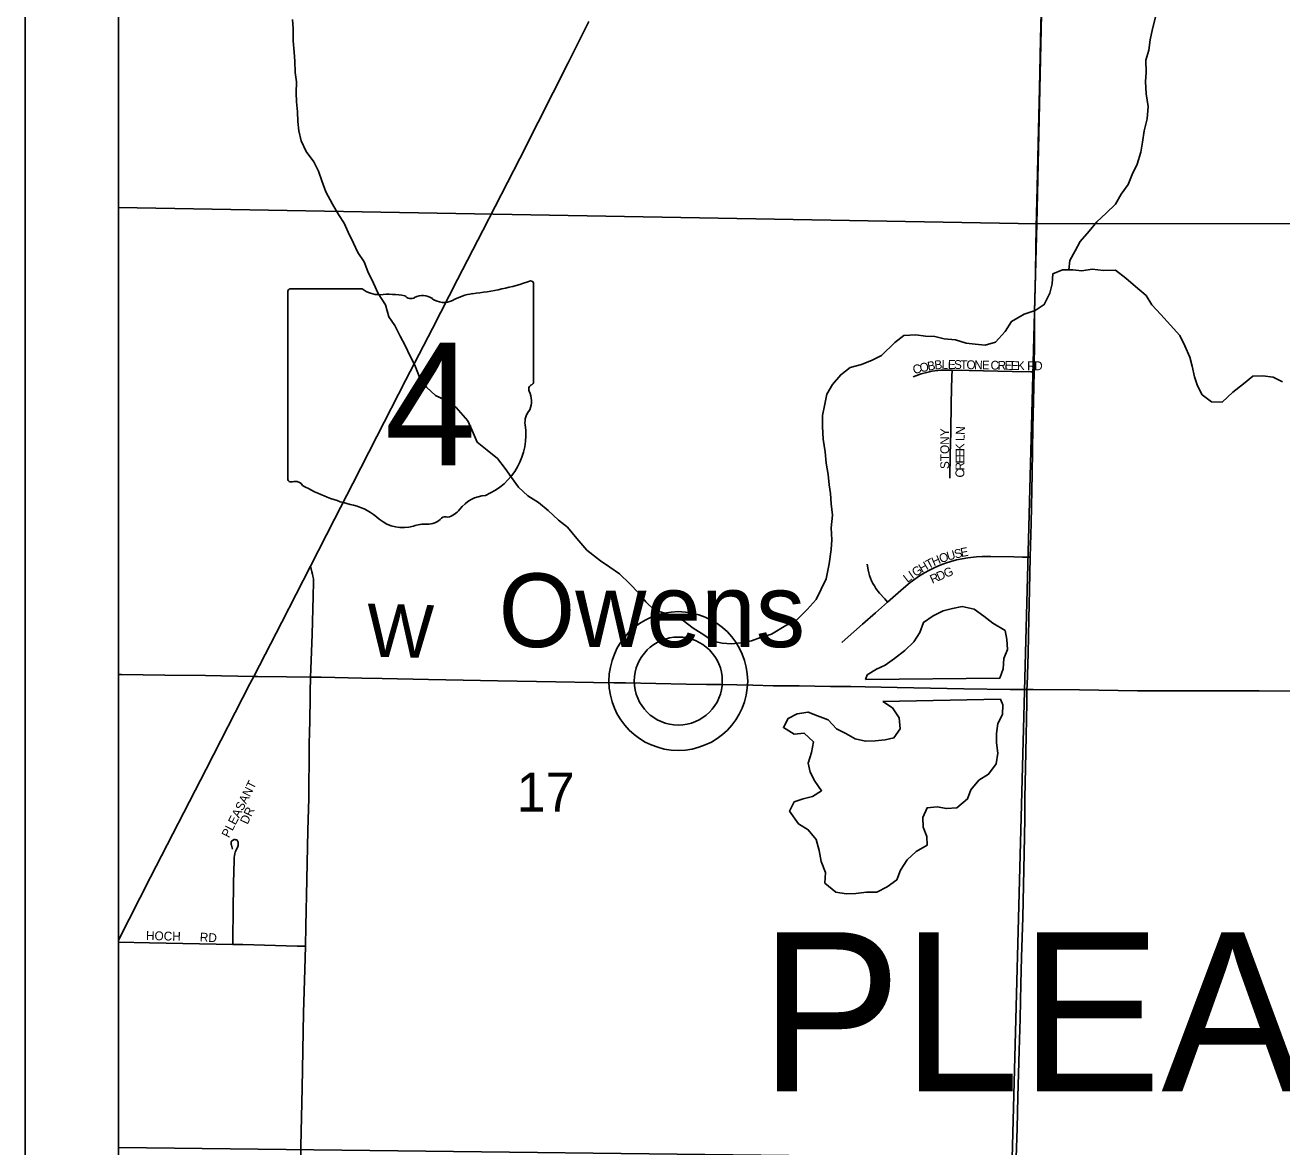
# Model space of a CAD drawing. Extents: x -97 to 34, y -21 to 22.
# Drawn here: x 3.451 to 4.799, y 14.464 to 15.667 of the extents above; entities that cross this region are included whole.
import ezdxf

# ---------------------------------------------------------------- set-up
doc = ezdxf.new("R2010")
doc.units = 0
for name, color, linetype in [('GM_X_County_Road', 7, 'Continuous'), ('GM_X_County_Road_Text', 7, 'Continuous'), ('GM_X_Minor_Lake', 7, 'Continuous'), ('GM_X_Minor_River', 7, 'Continuous'), ('GM_X_Section', 7, 'Continuous'), ('GM_X_Section_Text', 7, 'Continuous'), ('GM_X_State_Location', 7, 'Continuous'), ('GM_X_State_Route', 7, 'Continuous'), ('GM_X_State_Shield', 7, 'Continuous'), ('GM_X_Township_Subdivision', 7, 'Continuous'), ('GM_X_Township_Subdivision_Text', 7, 'Continuous'), ('GM_X_Township_Text', 7, 'Continuous'), ('GM_X_Unincorporated', 7, 'Continuous'), ('GM_X_Unincorporated_Location', 7, 'Continuous'), ('GM_X_Unincorporated_Text', 7, 'Continuous'), ('SH_Data', 7, 'Continuous')]:
    doc.layers.add(name, color=color, linetype=linetype)

msp = doc.modelspace()

# ---------------------------------------------------------------- linework, layer by layer
at = {"layer": 'GM_X_County_Road'}
for points in [[(4.5335, 15.2947), (4.5335, 15.2973), (4.5339, 15.3284), (4.5342, 15.3594), (4.5352, 15.3998), (4.5356, 15.4278), (4.5359, 15.4495), (4.5369, 15.493), (4.5379, 15.5396), (4.5394, 15.5986), (4.5405, 15.6514), (4.5417, 15.695), (4.5426, 15.7478), (4.5432, 15.7726), (4.5441, 15.8037), (4.5446, 15.8379), (4.5452, 15.8658), (4.546, 15.9124), (4.5468, 15.9435), (4.547, 15.959), (4.547, 15.9605)], [(4.5295, 15.0961), (4.5305, 15.1327), (4.5314, 15.1855), (4.5323, 15.2352), (4.533, 15.2631), (4.5335, 15.2947)], [(3.7576, 14.9675), (3.7578, 14.9762), (3.7593, 15.0135), (3.7603, 15.0538), (3.7607, 15.0698), (3.7606, 15.073), (3.7602, 15.0756), (3.7598, 15.0778), (3.7591, 15.0804), (3.7575, 15.0865)], [(4.5259, 14.9544), (4.526, 14.9587), (4.5272, 14.9929), (4.528, 15.0301), (4.5288, 15.0612), (4.5295, 15.0961)], [(3.5515, 14.9704), (3.5547, 14.9703), (3.6013, 14.9696), (3.6449, 14.9692), (3.6968, 14.9683)], [(3.6968, 14.9683), (3.7008, 14.9683), (3.7319, 14.9679), (3.7576, 14.9675)], [(3.752, 14.6791), (3.7526, 14.7006), (3.7537, 14.7506), (3.7548, 14.8031), (3.7557, 14.8376), (3.7559, 14.8557), (3.756, 14.8742), (3.7562, 14.899), (3.7564, 14.9051), (3.7571, 14.9422), (3.7573, 14.9514), (3.7576, 14.9675)], [(3.7576, 14.9675), (3.7691, 14.9673), (3.8126, 14.9665), (3.8344, 14.9661), (3.8841, 14.9651), (3.9586, 14.9637), (4.0208, 14.9623), (4.0611, 14.9617), (4.0829, 14.9615), (4.0953, 14.9613), (4.1605, 14.9599), (4.1822, 14.9596), (4.1977, 14.9595), (4.2319, 14.9588), (4.2536, 14.9582), (4.2815, 14.9581), (4.3153, 14.9576), (4.337, 14.9573), (4.3525, 14.957), (4.3866, 14.9562), (4.4581, 14.9548), (4.5078, 14.9544), (4.5259, 14.9544)], [(4.5028, 14.0177), (4.5034, 14.0361), (4.5047, 14.0827), (4.5064, 14.1573), (4.5074, 14.1977), (4.508, 14.2412), (4.5092, 14.2846), (4.5104, 14.3281), (4.5122, 14.3872), (4.5134, 14.4213), (4.5153, 14.4834), (4.5162, 14.5176), (4.5177, 14.5673), (4.5186, 14.6015), (4.5195, 14.6387), (4.5201, 14.6667), (4.5214, 14.7102), (4.523, 14.7785), (4.5235, 14.8158), (4.5238, 14.8375), (4.5248, 14.8872), (4.5257, 14.9401), (4.5259, 14.9544)], [(4.5259, 14.9544), (4.5326, 14.9543), (4.5823, 14.9538), (4.6444, 14.9529), (4.7034, 14.9529), (4.7314, 14.9528), (4.7749, 14.9529), (4.8339, 14.9526), (4.8773, 14.952), (4.9115, 14.9519), (4.9426, 14.9516), (4.9643, 14.9513), (5.0016, 14.9509), (5.0451, 14.9504), (5.0979, 14.9499), (5.1663, 14.9494), (5.2191, 14.949), (5.2719, 14.9485), (5.31, 14.948)], [(3.737, 14.0177), (3.7376, 14.0393), (3.7389, 14.0827), (3.74, 14.1386), (3.7418, 14.2163), (3.7428, 14.2722), (3.7441, 14.3249), (3.7463, 14.4243), (3.7471, 14.4647), (3.7486, 14.5268), (3.7501, 14.6075), (3.7513, 14.6541), (3.752, 14.6791)]]:
    msp.add_lwpolyline(points, dxfattribs=at)
at = {"layer": 'GM_X_Minor_Lake'}
for points in [[(4.4967, 14.9663), (4.5006, 14.9765), (4.5012, 14.9874), (4.5051, 14.9972), (4.5042, 15.0079), (4.5024, 15.0174), (4.4893, 15.0252), (4.4796, 15.0329), (4.4692, 15.0403), (4.4564, 15.0432), (4.4461, 15.0411), (4.4359, 15.0386), (4.4252, 15.0331), (4.4149, 15.0261), (4.4109, 15.0155), (4.4047, 15.0054), (4.3951, 14.9961), (4.384, 14.9876), (4.374, 14.9802), (4.3645, 14.9762), (4.3546, 14.9699), (4.3526, 14.965)], [(4.3526, 14.965), (4.4967, 14.9663)], [(4.3715, 14.9415), (4.3816, 14.9345), (4.389, 14.9238), (4.3899, 14.912), (4.3833, 14.9023), (4.3738, 14.9002), (4.3632, 14.8992), (4.3526, 14.8987), (4.3417, 14.9015), (4.3316, 14.907), (4.3215, 14.9121), (4.3126, 14.9217), (4.3013, 14.9261), (4.2912, 14.93), (4.2794, 14.928), (4.2699, 14.9232), (4.2648, 14.9134), (4.2764, 14.9064), (4.287, 14.9074), (4.2971, 14.8981), (4.295, 14.8868), (4.2914, 14.8751), (4.2935, 14.8656), (4.2986, 14.856), (4.3056, 14.8456), (4.2961, 14.8394), (4.2858, 14.8369), (4.2763, 14.8336), (4.2713, 14.8239), (4.2809, 14.8101), (4.2913, 14.8038), (4.2999, 14.7934), (4.3031, 14.7816), (4.3051, 14.7698), (4.3099, 14.758), (4.3093, 14.7466), (4.3208, 14.737), (4.3322, 14.7353), (4.3424, 14.7355), (4.3537, 14.7368), (4.3651, 14.737), (4.3761, 14.7428), (4.3865, 14.7502), (4.3904, 14.7604), (4.3974, 14.7717), (4.407, 14.7806), (4.4188, 14.7872), (4.4186, 14.7967), (4.4146, 14.8066), (4.4144, 14.8168), (4.4188, 14.8274), (4.4297, 14.8283), (4.4395, 14.8266), (4.4509, 14.8272), (4.462, 14.8369), (4.4656, 14.8467), (4.4744, 14.8571), (4.4848, 14.8634), (4.4929, 14.8746), (4.4946, 14.886), (4.4932, 14.897), (4.4934, 14.9072), (4.4947, 14.9178), (4.4998, 14.9276), (4.5, 14.9378), (4.4974, 14.9439)], [(4.4974, 14.9439), (4.3715, 14.9415)]]:
    msp.add_lwpolyline(points, dxfattribs=at)
at = {"layer": 'GM_X_Minor_River'}
for points in [[(4.5708, 15.4042), (4.5718, 15.4142), (4.5776, 15.4247), (4.5831, 15.4348), (4.5927, 15.4457), (4.6008, 15.4558), (4.6108, 15.4651), (4.6208, 15.4747), (4.627, 15.4852), (4.6344, 15.4957), (4.6387, 15.5063), (4.6442, 15.5176), (4.6482, 15.5304), (4.6499, 15.5413), (4.6516, 15.5534), (4.6548, 15.5663), (4.6558, 15.5795), (4.6538, 15.5928), (4.6532, 15.6061), (4.6538, 15.6159), (4.6536, 15.6292), (4.6568, 15.6398), (4.6581, 15.6507), (4.6606, 15.6625), (4.665, 15.6794)], [(3.7383, 15.6727), (3.7389, 15.6632), (3.7391, 15.6499), (3.74, 15.6378), (3.7406, 15.6279), (3.7411, 15.6158), (3.7425, 15.6059), (3.7423, 15.5942), (3.7425, 15.5843), (3.7435, 15.5737), (3.744, 15.5634), (3.745, 15.5532), (3.7475, 15.5425), (3.753, 15.5311), (3.7611, 15.5199), (3.7662, 15.51), (3.7698, 15.4997), (3.7738, 15.4879), (3.7811, 15.4748), (3.7874, 15.4637), (3.7937, 15.4542), (3.798, 15.4446), (3.8035, 15.4328)], [(3.8035, 15.4328), (3.8083, 15.4228), (3.8149, 15.4129), (3.8189, 15.4025), (3.8251, 15.3899), (3.8302, 15.3789), (3.8379, 15.3666), (3.8415, 15.354), (3.8478, 15.3444), (3.8536, 15.333), (3.8591, 15.323), (3.8643, 15.3115), (3.8694, 15.302), (3.8745, 15.289), (3.8819, 15.2786), (3.8915, 15.2694), (3.9017, 15.265), (3.9136, 15.2565), (3.9262, 15.2422), (3.931, 15.2319), (3.9364, 15.2193), (3.9469, 15.2108), (3.9581, 15.2019), (3.9662, 15.1911), (3.9732, 15.1815), (3.9806, 15.1712), (3.9907, 15.1619), (4.0019, 15.1549), (4.0123, 15.146), (4.0235, 15.1359), (4.0332, 15.1282), (4.0432, 15.1163), (4.054, 15.1036), (4.0685, 15.0923), (4.0786, 15.0853), (4.0891, 15.0783), (4.0999, 15.0675), (4.1092, 15.0579), (4.117, 15.0483), (4.1266, 15.0394), (4.1364, 15.0366), (4.1462, 15.0326), (4.1571, 15.0283), (4.1679, 15.0201), (4.1795, 15.0127), (4.1892, 15.0061), (4.199, 15.004), (4.2092, 15.0031), (4.2194, 15.0044), (4.2304, 15.0065), (4.2403, 15.0101), (4.2521, 15.0137), (4.2674, 15.0229), (4.2788, 15.0284), (4.2903, 15.04), (4.3, 15.0508), (4.3054, 15.0617), (4.3105, 15.073), (4.3138, 15.0889), (4.316, 15.1044), (4.3165, 15.1146), (4.316, 15.1275), (4.3174, 15.1411), (4.316, 15.1533), (4.3151, 15.1643), (4.3137, 15.1738), (4.3128, 15.1848), (4.3107, 15.1969), (4.3094, 15.2091), (4.3074, 15.2228), (4.3065, 15.2364), (4.3067, 15.2482), (4.3091, 15.2603), (4.3112, 15.2708), (4.3174, 15.2814), (4.3263, 15.2918), (4.3362, 15.2996), (4.3484, 15.3028), (4.3598, 15.3075), (4.3701, 15.3123), (4.3843, 15.3264), (4.3939, 15.3339), (4.4068, 15.3344), (4.4173, 15.3331), (4.4271, 15.3329), (4.4373, 15.3301), (4.4494, 15.3291), (4.4607, 15.3255), (4.4705, 15.3246), (4.481, 15.3233), (4.4921, 15.3265), (4.5025, 15.3381), (4.5094, 15.3489), (4.5228, 15.3567), (4.5346, 15.3606), (4.5445, 15.3669), (4.5504, 15.3793), (4.5528, 15.3891), (4.5538, 15.4001), (4.564, 15.4041), (4.575, 15.4043)], [(4.575, 15.4043), (4.5848, 15.4033), (4.5958, 15.405), (4.6079, 15.4037), (4.6208, 15.4039), (4.632, 15.3953), (4.6424, 15.3864), (4.6539, 15.3767), (4.6598, 15.3668), (4.6695, 15.3564), (4.6799, 15.3448), (4.6899, 15.3337), (4.6954, 15.3226), (4.7005, 15.3107), (4.7033, 15.3008), (4.7058, 15.2894), (4.709, 15.2799), (4.7138, 15.2703), (4.7239, 15.2626), (4.7352, 15.2624), (4.7467, 15.2732), (4.7582, 15.2821), (4.7682, 15.2902), (4.7788, 15.2904), (4.7901, 15.2891), (4.7999, 15.284)]]:
    msp.add_lwpolyline(points, dxfattribs=at)
at = {"layer": 'GM_X_Section'}
for p, q in [((3.5515, 16.4817), (3.5515, 15.4711)), ((3.5515, 15.4711), (3.5515, 14.463))]:
    msp.add_line(p, q, dxfattribs=at)
for points in [[(3.5515, 15.4711), (4.5367, 15.4537), (4.5591, 16.4647), (3.5515, 16.4817)], [(3.5515, 14.463), (4.5101, 14.4515), (4.5367, 15.4537), (3.5515, 15.4711)]]:
    msp.add_lwpolyline(points, dxfattribs=at)
for points in [[(4.5591, 16.4647), (5.5865, 16.4584), (5.5758, 15.4541), (4.5367, 15.4537)], [(4.5367, 15.4537), (5.5758, 15.4541), (5.5564, 14.4458), (4.5101, 14.4515)]]:
    msp.add_lwpolyline(points, close=True, dxfattribs=at)
at = {"layer": 'GM_X_State_Route'}
msp.add_lwpolyline([(3.5515, 14.6855), (3.586, 14.753), (3.6457, 14.8689), (3.6925, 14.9602), (3.6968, 14.9683), (3.7268, 15.0263), (3.7575, 15.0865), (3.7833, 15.137), (3.8028, 15.1751), (3.8286, 15.2254), (3.8599, 15.2862), (3.8883, 15.3415), (3.9153, 15.3939), (3.9422, 15.4464), (3.9821, 15.5238), (4.0017, 15.5625), (4.0339, 15.6263), (4.0561, 15.6707)], dxfattribs=at)
at = {"layer": 'GM_X_State_Shield'}
for p, q in [((3.7332, 15.3805), (3.7332, 15.1804)), ((3.813, 15.384), (3.7358, 15.384)), ((3.9968, 15.2843), (3.9968, 15.389)), ((3.9968, 15.2843), (3.9968, 15.2843))]:
    msp.add_line(p, q, dxfattribs=at)
for centre, radius, start, end in [((3.7362, 15.381), 0.00305, 98.1301, 188.1301), ((3.8314, 15.4072), 0.0296, 231.6195, 271.1119), ((3.9029, 15.6568), 0.2796, 275.8445, 288.9065), ((3.9939, 15.3894), 0.00294, 351.8621, 97.738), ((3.8412, 15.2716), 0.1064, 80.4867, 94.9883), ((3.8653, 15.382), 0.00855, 219.7921, 297.1024), ((3.8779, 15.3589), 0.0178, 54.4667, 119.1411), ((3.9008, 15.3906), 0.0214, 233.8562, 294.8282), ((3.9386, 15.3229), 0.0563, 97.3462, 120.7689), ((3.9961, 15.2766), 0.00454, 107.944, 210.337), ((3.9672, 15.2633), 0.0273, 340.033, 23.6496), ((3.9937, 15.2839), 0.00314, 289.6038, 7.7341), ((4.0073, 15.2405), 0.0198, 136.8065, 186.9296), ((3.9186, 15.2271), 0.0699, 292.3089, 8.9858), ((3.7362, 15.18), 0.00308, 171.9584, 258.3066), ((3.7367, 15.2005), 0.0235, 267.339, 280.6039), ((3.7415, 15.1689), 0.00848, 29.7484, 93.2717), ((3.8485, 15.3487), 0.2019, 240.4129, 257.1985), ((3.7883, 15.0905), 0.0632, 47.1842, 75.836), ((3.9481, 15.1242), 0.0383, 94.4031, 142.5768), ((3.8567, 15.1679), 0.0401, 230.7004, 286.2918), ((3.8828, 15.1529), 0.0214, 268.777, 315.5493), ((3.9021, 15.1335), 0.00601, 65.7517, 132.6484), ((3.8995, 15.161), 0.0226, 282.8732, 323.2771), ((3.8798, 15.0987), 0.0329, 85.6951, 111.2099)]:
    msp.add_arc(centre, radius, start, end, dxfattribs=at)
at = {"layer": 'GM_X_Township_Subdivision'}
for points in [[(4.404, 15.2894), (4.4069, 15.2905), (4.4126, 15.2926), (4.4184, 15.2943), (4.4214, 15.295), (4.4243, 15.2955), (4.4273, 15.296), (4.4334, 15.2965), (4.4425, 15.2967), (4.4456, 15.2967)], [(4.4434, 15.181), (4.4436, 15.2059), (4.4442, 15.2307), (4.4448, 15.2618), (4.4454, 15.2897), (4.4456, 15.2967)], [(4.4456, 15.2967), (4.464, 15.2963), (4.51, 15.2953), (4.53, 15.2948), (4.5335, 15.2947)], [(4.5295, 15.0961), (4.5212, 15.0961), (4.512, 15.0964), (4.4872, 15.0969), (4.4779, 15.0968), (4.4718, 15.0965), (4.4625, 15.0955), (4.4564, 15.0945), (4.4504, 15.0932), (4.4444, 15.0916), (4.4386, 15.0896), (4.4328, 15.0874), (4.4271, 15.0849), (4.4215, 15.0823), (4.4161, 15.0793), (4.4108, 15.0761), (4.4057, 15.0727), (4.4008, 15.0689), (4.3936, 15.063), (4.3765, 15.048)], [(4.3765, 15.048), (4.3734, 15.0514), (4.3677, 15.0576), (4.364, 15.0626), (4.3623, 15.0653), (4.3607, 15.068), (4.3593, 15.0707), (4.3581, 15.0736), (4.357, 15.0765), (4.3562, 15.0795), (4.3555, 15.0826), (4.3545, 15.0887)], [(4.3765, 15.048), (4.3634, 15.0365), (4.3495, 15.0242), (4.331, 15.0078), (4.3273, 15.0046)], [(3.6742, 14.6809), (3.6742, 14.6884), (3.6744, 14.716), (3.6751, 14.7467), (3.6755, 14.7713), (3.6757, 14.7744), (3.6759, 14.7759), (3.6765, 14.7785), (3.6769, 14.7798), (3.6775, 14.7813), (3.6795, 14.786), (3.6799, 14.7869), (3.6801, 14.788), (3.6801, 14.789), (3.68, 14.7898), (3.6799, 14.7906), (3.6797, 14.7912), (3.6793, 14.7919), (3.6787, 14.7925), (3.6781, 14.7929), (3.6773, 14.7931), (3.6765, 14.7933), (3.6757, 14.7933), (3.675, 14.7931), (3.6744, 14.7928), (3.6738, 14.7924), (3.6733, 14.7918), (3.6729, 14.7912), (3.6726, 14.7905), (3.6725, 14.7897), (3.6725, 14.7882), (3.6727, 14.7874), (3.6739, 14.783)], [(3.5515, 14.6833), (3.5849, 14.6825), (3.6742, 14.6809)], [(3.6742, 14.6809), (3.6849, 14.6807), (3.7432, 14.6791), (3.7489, 14.6791), (3.752, 14.6791)]]:
    msp.add_lwpolyline(points, dxfattribs=at)
at = {"layer": 'GM_X_Unincorporated'}
for radius in [0.0744, 0.0472]:
    msp.add_circle((4.152, 14.9633), radius, dxfattribs=at)
at = {"layer": 'GM_X_Unincorporated_Location'}
msp.add_line((4.152, 14.9633), (4.152, 14.9633), dxfattribs=at)
at = {"layer": 'SH_Data'}
for p, q in [((3.4515, 20.9177), (3.4515, 13.9177)), ((3.5515, 20.8177), (3.5515, 14.0177))]:
    msp.add_line(p, q, dxfattribs=at)

# ---------------------------------------------------------------- texts
at = {"layer": 'GM_X_County_Road_Text'}
msp.add_text('W', height=0.0568, rotation=358.5554, dxfattribs=at).set_placement((3.8173, 14.9896))
at = {"layer": 'GM_X_Section_Text'}
msp.add_text('17', height=0.04186, rotation=0, dxfattribs=at).set_placement((3.9785, 14.8233))
at = {"layer": 'GM_X_State_Location'}
for s in ['s', 'r']:
    msp.add_text(s, height=0.000189, dxfattribs=at).set_placement((3.862, 15.2672))
msp.add_text('4', height=0.000189, rotation=0, dxfattribs=at).set_placement((3.8335, 15.2534))
at = {"layer": 'GM_X_State_Shield'}
msp.add_text('4', height=0.1318, dxfattribs=at).set_placement((3.837, 15.1945))
at = {"layer": 'GM_X_Township_Subdivision_Text'}
for s, rotation, p in [('C', 13.8301, (4.4047, 15.2923)), ('O', 13.0077, (4.412, 15.2941)), ('B', 10.1571, (4.42, 15.296)), ('B', 6.646, (4.4272, 15.2973)), ('L', 359.6448, (4.4343, 15.2981)), ('E', 359.0984, (4.441, 15.2981)), ('S', 359.0165, (4.4476, 15.298)), ('T', 359.0279, (4.4543, 15.2979)), ('O', 359.0164, (4.461, 15.2978)), ('N', 359.0244, (4.4693, 15.2976)), ('E', 359.0416, (4.4776, 15.2975)), ('C', 359.0286, (4.4868, 15.2973)), ('R', 359.0043, (4.4943, 15.2972)), ('E', 359.0279, (4.5018, 15.2971)), ('E', 359.0165, (4.5085, 15.2969)), ('K', 359.0244, (4.5151, 15.2968)), ('R', 359.4597, (4.5261, 15.2966)), ('D', 359.9703, (4.5336, 15.2966)), ('STONY', 90, (4.4425, 15.1906)), ('N', 86.5014, (4.459, 15.2271)), ('L', 89.0711, (4.4589, 15.2206)), ('K', 89.9126, (4.4588, 15.2098)), ('E', 90, (4.4588, 15.2031)), ('E', 90, (4.4588, 15.1965)), ('R', 90, (4.4588, 15.189)), ('C', 90, (4.4588, 15.1815)), ('H', 23.4454, (4.4261, 15.0863)), ('O', 19.4994, (4.4336, 15.0896)), ('U', 15.7803, (4.4413, 15.0923)), ('S', 14.3278, (4.4492, 15.0945)), ('E', 10.6348, (4.4555, 15.0962)), ('G', 33.1687, (4.4064, 15.0747)), ('H', 30.2627, (4.4132, 15.0792)), ('T', 27.4938, (4.4203, 15.0833)), ('G', 21.0344, (4.4388, 15.0739)), ('L', 37.9301, (4.3978, 15.0683)), ('I', 34.3689, (4.403, 15.0724)), ('R', 24.5987, (4.4245, 15.0674)), ('D', 24.0712, (4.4313, 15.0705)), ('PLEASANT', 63.0739, (3.67, 14.7945)), ('DR', 64.7982, (3.69, 14.8089)), ('HOCH', 358.5321, (3.581, 14.6857)), ('RD', 356.989, (3.6386, 14.6841))]:
    msp.add_text(s, height=0.00947, rotation=rotation, dxfattribs=at).set_placement(p)
at = {"layer": 'GM_X_Township_Text'}
msp.add_text('PLEASANT TWP.', height=0.170455, rotation=0, dxfattribs=at).set_placement((4.2393, 14.5235))
at = {"layer": 'GM_X_Unincorporated_Text'}
msp.add_text('Owens', height=0.07898, rotation=0, dxfattribs=at).set_placement((3.9593, 14.9997))

doc.saveas('drawing.dxf')
